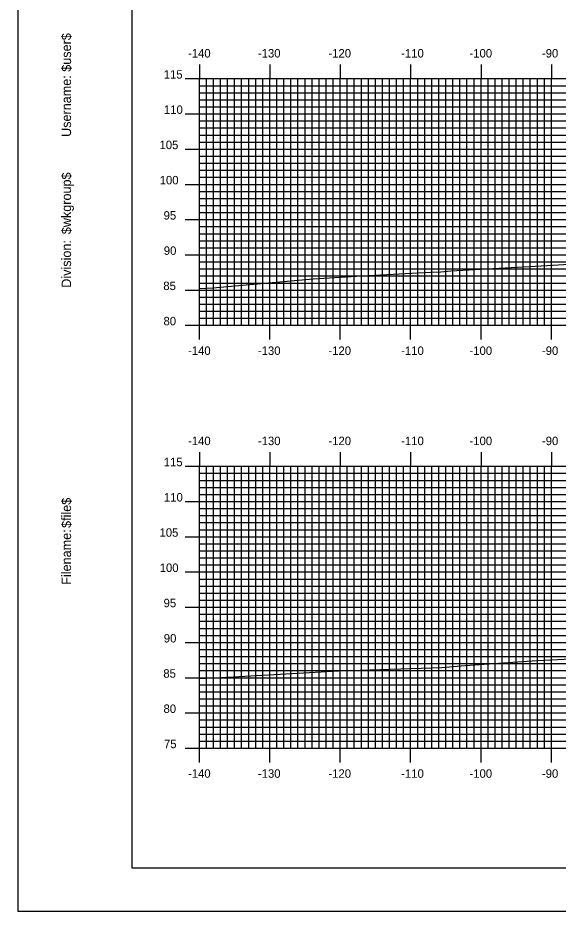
# Model space of a CAD drawing. Extents: x 879 to 1222, y -1658 to -1438.
# Drawn here: x 878.9 to 955.6, y -1657.7 to -1531 of the extents above; entities that cross this region are included whole.
import ezdxf

# ---------------------------------------------------------------- set-up
doc = ezdxf.new("R2010")
doc.units = 0
for name, color, linetype in [('BORDER', 7, 'Continuous'), ('H_V ANNOTATION', 7, 'Continuous'), ('MAJOR', 7, 'Continuous'), ('MINOR', 7, 'Continuous'), ('PLOT BOUNDARY', 7, 'Continuous'), ('S_Roadway_Centerline', 7, 'Continuous')]:
    doc.layers.add(name, color=color, linetype=linetype)

msp = doc.modelspace()

# ---------------------------------------------------------------- linework, layer by layer
at = {"layer": 'BORDER'}
msp.add_lwpolyline([(895.05, -1651.6), (1215.05, -1651.6), (1215.05, -1441.6), (895.05, -1441.6)], close=True, dxfattribs=at)
at = {"layer": 'MAJOR'}
for p, q in [((904.65, -1537.6), (904.65, -1539.6)), ((914.65, -1537.6), (914.65, -1539.6)), ((924.65, -1537.6), (924.65, -1539.6)), ((934.65, -1537.6), (934.65, -1539.6)), ((944.65, -1537.6), (944.65, -1539.6)), ((954.65, -1537.6), (954.65, -1539.6)), ((902.64, -1539.6), (904.65, -1539.6)), ((904.65, -1539.6), (1184.65, -1539.6)), ((904.65, -1574.6), (904.65, -1539.6)), ((904.65, -1574.6), (904.65, -1539.6)), ((904.65, -1539.6), (1184.65, -1539.6)), ((914.65, -1574.6), (914.65, -1539.6)), ((924.65, -1574.6), (924.65, -1539.6)), ((934.65, -1574.6), (934.65, -1539.6)), ((944.65, -1574.6), (944.65, -1539.6)), ((954.65, -1574.6), (954.65, -1539.6)), ((902.64, -1544.6), (904.65, -1544.6)), ((904.65, -1544.6), (1184.65, -1544.6)), ((902.64, -1549.6), (904.65, -1549.6)), ((904.65, -1549.6), (1184.65, -1549.6)), ((902.64, -1554.6), (904.65, -1554.6)), ((904.65, -1554.6), (1184.65, -1554.6)), ((902.64, -1559.6), (904.65, -1559.6)), ((904.65, -1559.6), (1184.65, -1559.6)), ((902.64, -1564.6), (904.65, -1564.6)), ((904.65, -1564.6), (1184.65, -1564.6)), ((902.64, -1569.6), (904.65, -1569.6)), ((904.65, -1569.6), (1184.65, -1569.6)), ((902.64, -1574.6), (904.65, -1574.6)), ((904.65, -1574.6), (1184.65, -1574.6)), ((904.65, -1574.6), (1184.65, -1574.6)), ((904.65, -1576.61), (904.65, -1574.6)), ((914.65, -1576.61), (914.65, -1574.6)), ((924.65, -1576.61), (924.65, -1574.6)), ((934.65, -1576.61), (934.65, -1574.6)), ((944.65, -1576.61), (944.65, -1574.6)), ((954.65, -1576.61), (954.65, -1574.6)), ((904.65, -1592.6), (904.65, -1594.6)), ((914.65, -1592.6), (914.65, -1594.6)), ((924.65, -1592.6), (924.65, -1594.6)), ((934.65, -1592.6), (934.65, -1594.6)), ((944.65, -1592.6), (944.65, -1594.6)), ((954.65, -1592.6), (954.65, -1594.6)), ((902.64, -1594.6), (904.65, -1594.6)), ((904.65, -1594.6), (1184.65, -1594.6)), ((904.65, -1634.6), (904.65, -1594.6)), ((904.65, -1634.6), (904.65, -1594.6)), ((904.65, -1594.6), (1184.65, -1594.6)), ((914.65, -1634.6), (914.65, -1594.6)), ((924.65, -1634.6), (924.65, -1594.6)), ((934.65, -1634.6), (934.65, -1594.6)), ((944.65, -1634.6), (944.65, -1594.6)), ((954.65, -1634.6), (954.65, -1594.6)), ((902.64, -1599.6), (904.65, -1599.6)), ((904.65, -1599.6), (1184.65, -1599.6)), ((902.64, -1604.6), (904.65, -1604.6)), ((904.65, -1604.6), (1184.65, -1604.6)), ((902.64, -1609.6), (904.65, -1609.6)), ((904.65, -1609.6), (1184.65, -1609.6)), ((902.64, -1614.6), (904.65, -1614.6)), ((904.65, -1614.6), (1184.65, -1614.6)), ((902.64, -1619.6), (904.65, -1619.6)), ((904.65, -1619.6), (1184.65, -1619.6)), ((902.64, -1624.6), (904.65, -1624.6)), ((904.65, -1624.6), (1184.65, -1624.6)), ((902.64, -1629.6), (904.65, -1629.6)), ((904.65, -1629.6), (1184.65, -1629.6)), ((902.64, -1634.6), (904.65, -1634.6)), ((904.65, -1634.6), (1184.65, -1634.6)), ((904.65, -1634.6), (1184.65, -1634.6)), ((904.65, -1636.61), (904.65, -1634.6)), ((914.65, -1636.61), (914.65, -1634.6)), ((924.65, -1636.61), (924.65, -1634.6)), ((934.65, -1636.61), (934.65, -1634.6)), ((944.65, -1636.61), (944.65, -1634.6)), ((954.65, -1636.61), (954.65, -1634.6))]:
    msp.add_line(p, q, dxfattribs=at)
at = {"layer": 'MINOR'}
for p, q in [((905.65, -1574.6), (905.65, -1539.6)), ((906.65, -1574.6), (906.65, -1539.6)), ((907.65, -1574.6), (907.65, -1539.6)), ((908.65, -1574.6), (908.65, -1539.6)), ((909.65, -1574.6), (909.65, -1539.6)), ((910.65, -1574.6), (910.65, -1539.6)), ((911.65, -1574.6), (911.65, -1539.6)), ((912.65, -1574.6), (912.65, -1539.6)), ((913.65, -1574.6), (913.65, -1539.6)), ((915.65, -1574.6), (915.65, -1539.6)), ((916.65, -1574.6), (916.65, -1539.6)), ((917.65, -1574.6), (917.65, -1539.6)), ((918.65, -1574.6), (918.65, -1539.6)), ((919.65, -1574.6), (919.65, -1539.6)), ((920.65, -1574.6), (920.65, -1539.6)), ((921.65, -1574.6), (921.65, -1539.6)), ((922.65, -1574.6), (922.65, -1539.6)), ((923.65, -1574.6), (923.65, -1539.6)), ((925.65, -1574.6), (925.65, -1539.6)), ((926.65, -1574.6), (926.65, -1539.6)), ((927.65, -1574.6), (927.65, -1539.6)), ((928.65, -1574.6), (928.65, -1539.6)), ((929.65, -1574.6), (929.65, -1539.6)), ((930.65, -1574.6), (930.65, -1539.6)), ((931.65, -1574.6), (931.65, -1539.6)), ((932.65, -1574.6), (932.65, -1539.6)), ((933.65, -1574.6), (933.65, -1539.6)), ((935.65, -1574.6), (935.65, -1539.6)), ((936.65, -1574.6), (936.65, -1539.6)), ((937.65, -1574.6), (937.65, -1539.6)), ((938.65, -1574.6), (938.65, -1539.6)), ((939.65, -1574.6), (939.65, -1539.6)), ((940.65, -1574.6), (940.65, -1539.6)), ((941.65, -1574.6), (941.65, -1539.6)), ((942.65, -1574.6), (942.65, -1539.6)), ((943.65, -1574.6), (943.65, -1539.6)), ((945.65, -1574.6), (945.65, -1539.6)), ((946.65, -1574.6), (946.65, -1539.6)), ((947.65, -1574.6), (947.65, -1539.6)), ((948.65, -1574.6), (948.65, -1539.6)), ((949.65, -1574.6), (949.65, -1539.6)), ((950.65, -1574.6), (950.65, -1539.6)), ((951.65, -1574.6), (951.65, -1539.6)), ((952.65, -1574.6), (952.65, -1539.6)), ((953.65, -1574.6), (953.65, -1539.6)), ((904.65, -1540.6), (1184.65, -1540.6)), ((904.65, -1540.6), (906.65, -1540.6)), ((904.65, -1541.6), (1184.65, -1541.6)), ((904.65, -1541.6), (906.65, -1541.6)), ((904.65, -1542.6), (1184.65, -1542.6)), ((904.65, -1542.6), (906.65, -1542.6)), ((904.65, -1543.6), (1184.65, -1543.6)), ((904.65, -1543.6), (906.65, -1543.6)), ((904.65, -1545.6), (1184.65, -1545.6)), ((904.65, -1545.6), (906.65, -1545.6)), ((904.65, -1546.6), (1184.65, -1546.6)), ((904.65, -1546.6), (906.65, -1546.6)), ((904.65, -1547.6), (1184.65, -1547.6)), ((904.65, -1547.6), (906.65, -1547.6)), ((904.65, -1548.6), (1184.65, -1548.6)), ((904.65, -1548.6), (906.65, -1548.6)), ((904.65, -1550.6), (1184.65, -1550.6)), ((904.65, -1550.6), (906.65, -1550.6)), ((904.65, -1551.6), (1184.65, -1551.6)), ((904.65, -1551.6), (906.65, -1551.6)), ((904.65, -1552.6), (1184.65, -1552.6)), ((904.65, -1552.6), (906.65, -1552.6)), ((904.65, -1553.6), (1184.65, -1553.6)), ((904.65, -1553.6), (906.65, -1553.6)), ((904.65, -1555.6), (1184.65, -1555.6)), ((904.65, -1555.6), (906.65, -1555.6)), ((904.65, -1556.6), (1184.65, -1556.6)), ((904.65, -1556.6), (906.65, -1556.6)), ((904.65, -1557.6), (1184.65, -1557.6)), ((904.65, -1557.6), (906.65, -1557.6)), ((904.65, -1558.6), (1184.65, -1558.6)), ((904.65, -1558.6), (906.65, -1558.6)), ((904.65, -1560.6), (1184.65, -1560.6)), ((904.65, -1560.6), (906.65, -1560.6)), ((904.65, -1561.6), (1184.65, -1561.6)), ((904.65, -1561.6), (906.65, -1561.6)), ((904.65, -1562.6), (1184.65, -1562.6)), ((904.65, -1562.6), (906.65, -1562.6)), ((904.65, -1563.6), (1184.65, -1563.6)), ((904.65, -1563.6), (906.65, -1563.6)), ((904.65, -1565.6), (1184.65, -1565.6)), ((904.65, -1565.6), (906.65, -1565.6)), ((904.65, -1566.6), (1184.65, -1566.6)), ((904.65, -1566.6), (906.65, -1566.6)), ((904.65, -1567.6), (1184.65, -1567.6)), ((904.65, -1567.6), (906.65, -1567.6)), ((904.65, -1568.6), (1184.65, -1568.6)), ((904.65, -1568.6), (906.65, -1568.6)), ((904.65, -1570.6), (1184.65, -1570.6)), ((904.65, -1570.6), (906.65, -1570.6)), ((904.65, -1571.6), (1184.65, -1571.6)), ((904.65, -1571.6), (906.65, -1571.6)), ((904.65, -1572.6), (1184.65, -1572.6)), ((904.65, -1572.6), (906.65, -1572.6)), ((904.65, -1573.6), (1184.65, -1573.6)), ((904.65, -1573.6), (906.65, -1573.6)), ((904.65, -1595.6), (1184.65, -1595.6)), ((904.65, -1595.6), (906.65, -1595.6)), ((905.65, -1634.6), (905.65, -1594.6)), ((906.65, -1634.6), (906.65, -1594.6)), ((907.65, -1634.6), (907.65, -1594.6)), ((908.65, -1634.6), (908.65, -1594.6)), ((909.65, -1634.6), (909.65, -1594.6)), ((910.65, -1634.6), (910.65, -1594.6)), ((911.65, -1634.6), (911.65, -1594.6)), ((912.65, -1634.6), (912.65, -1594.6)), ((913.65, -1634.6), (913.65, -1594.6)), ((915.65, -1634.6), (915.65, -1594.6)), ((916.65, -1634.6), (916.65, -1594.6)), ((917.65, -1634.6), (917.65, -1594.6)), ((918.65, -1634.6), (918.65, -1594.6)), ((919.65, -1634.6), (919.65, -1594.6)), ((920.65, -1634.6), (920.65, -1594.6)), ((921.65, -1634.6), (921.65, -1594.6)), ((922.65, -1634.6), (922.65, -1594.6)), ((923.65, -1634.6), (923.65, -1594.6)), ((925.65, -1634.6), (925.65, -1594.6)), ((926.65, -1634.6), (926.65, -1594.6)), ((927.65, -1634.6), (927.65, -1594.6)), ((928.65, -1634.6), (928.65, -1594.6)), ((929.65, -1634.6), (929.65, -1594.6)), ((930.65, -1634.6), (930.65, -1594.6)), ((931.65, -1634.6), (931.65, -1594.6)), ((932.65, -1634.6), (932.65, -1594.6)), ((933.65, -1634.6), (933.65, -1594.6)), ((935.65, -1634.6), (935.65, -1594.6)), ((936.65, -1634.6), (936.65, -1594.6)), ((937.65, -1634.6), (937.65, -1594.6)), ((938.65, -1634.6), (938.65, -1594.6)), ((939.65, -1634.6), (939.65, -1594.6)), ((940.65, -1634.6), (940.65, -1594.6)), ((941.65, -1634.6), (941.65, -1594.6)), ((942.65, -1634.6), (942.65, -1594.6)), ((943.65, -1634.6), (943.65, -1594.6)), ((945.65, -1634.6), (945.65, -1594.6)), ((946.65, -1634.6), (946.65, -1594.6)), ((947.65, -1634.6), (947.65, -1594.6)), ((948.65, -1634.6), (948.65, -1594.6)), ((949.65, -1634.6), (949.65, -1594.6)), ((950.65, -1634.6), (950.65, -1594.6)), ((951.65, -1634.6), (951.65, -1594.6)), ((952.65, -1634.6), (952.65, -1594.6)), ((953.65, -1634.6), (953.65, -1594.6)), ((904.65, -1596.6), (1184.65, -1596.6)), ((904.65, -1596.6), (906.65, -1596.6)), ((904.65, -1597.6), (1184.65, -1597.6)), ((904.65, -1597.6), (906.65, -1597.6)), ((904.65, -1598.6), (1184.65, -1598.6)), ((904.65, -1598.6), (906.65, -1598.6)), ((904.65, -1600.6), (1184.65, -1600.6)), ((904.65, -1600.6), (906.65, -1600.6)), ((904.65, -1601.6), (1184.65, -1601.6)), ((904.65, -1601.6), (906.65, -1601.6)), ((904.65, -1602.6), (1184.65, -1602.6)), ((904.65, -1602.6), (906.65, -1602.6)), ((904.65, -1603.6), (1184.65, -1603.6)), ((904.65, -1603.6), (906.65, -1603.6)), ((904.65, -1605.6), (1184.65, -1605.6)), ((904.65, -1605.6), (906.65, -1605.6)), ((904.65, -1606.6), (1184.65, -1606.6)), ((904.65, -1606.6), (906.65, -1606.6)), ((904.65, -1607.6), (1184.65, -1607.6)), ((904.65, -1607.6), (906.65, -1607.6)), ((904.65, -1608.6), (1184.65, -1608.6)), ((904.65, -1608.6), (906.65, -1608.6)), ((904.65, -1610.6), (1184.65, -1610.6)), ((904.65, -1610.6), (906.65, -1610.6)), ((904.65, -1611.6), (1184.65, -1611.6)), ((904.65, -1611.6), (906.65, -1611.6)), ((904.65, -1612.6), (1184.65, -1612.6)), ((904.65, -1612.6), (906.65, -1612.6)), ((904.65, -1613.6), (1184.65, -1613.6)), ((904.65, -1613.6), (906.65, -1613.6)), ((904.65, -1615.6), (1184.65, -1615.6)), ((904.65, -1615.6), (906.65, -1615.6)), ((904.65, -1616.6), (1184.65, -1616.6)), ((904.65, -1616.6), (906.65, -1616.6)), ((904.65, -1617.6), (1184.65, -1617.6)), ((904.65, -1617.6), (906.65, -1617.6)), ((904.65, -1618.6), (1184.65, -1618.6)), ((904.65, -1618.6), (906.65, -1618.6)), ((904.65, -1620.6), (1184.65, -1620.6)), ((904.65, -1620.6), (906.65, -1620.6)), ((904.65, -1621.6), (1184.65, -1621.6)), ((904.65, -1621.6), (906.65, -1621.6)), ((904.65, -1622.6), (1184.65, -1622.6)), ((904.65, -1622.6), (906.65, -1622.6)), ((904.65, -1623.6), (1184.65, -1623.6)), ((904.65, -1623.6), (906.65, -1623.6)), ((904.65, -1625.6), (1184.65, -1625.6)), ((904.65, -1625.6), (906.65, -1625.6)), ((904.65, -1626.6), (1184.65, -1626.6)), ((904.65, -1626.6), (906.65, -1626.6)), ((904.65, -1627.6), (1184.65, -1627.6)), ((904.65, -1627.6), (906.65, -1627.6)), ((904.65, -1628.6), (1184.65, -1628.6)), ((904.65, -1628.6), (906.65, -1628.6)), ((904.65, -1630.6), (1184.65, -1630.6)), ((904.65, -1630.6), (906.65, -1630.6)), ((904.65, -1631.6), (1184.65, -1631.6)), ((904.65, -1631.6), (906.65, -1631.6)), ((904.65, -1632.6), (1184.65, -1632.6)), ((904.65, -1632.6), (906.65, -1632.6)), ((904.65, -1633.6), (1184.65, -1633.6)), ((904.65, -1633.6), (906.65, -1633.6))]:
    msp.add_line(p, q, dxfattribs=at)
at = {"layer": 'PLOT BOUNDARY'}
msp.add_lwpolyline([(878.86, -1657.72), (1218.86, -1657.72), (1218.86, -1437.72), (878.86, -1437.72)], close=True, dxfattribs=at)
at = {"layer": 'S_Roadway_Centerline'}
for points in [[(904.65, -1569.39), (906.57, -1569.27), (920.82, -1568), (927.72, -1567.6), (937.47, -1567.07), (938.95, -1567), (940.37, -1566.88), (954.06, -1566.11), (957.1, -1565.94), (970.54, -1565.45), (981.3, -1564.54), (986.76, -1564.33), (997.58, -1564.13), (1003.63, -1564.01), (1010.92, -1563.72), (1020.27, -1563.67), (1029.13, -1563.37), (1035.94, -1563.09)], [(904.65, -1624.72), (905.67, -1624.65), (909.42, -1624.47), (921.92, -1623.77), (925.24, -1623.6), (926.03, -1623.57), (939.03, -1623.13), (942.41, -1622.85), (952.55, -1622.18), (959.41, -1621.83), (966.93, -1621.24), (977.01, -1620.75), (981.23, -1620.64), (993.73, -1620.44), (997.78, -1620.14), (1010.31, -1619.24), (1022, -1619.15), (1027.5, -1618.88), (1036.74, -1618.64)]]:
    msp.add_lwpolyline(points, dxfattribs=at)

# ---------------------------------------------------------------- texts
at = {"layer": 'BORDER'}
for s, p in [('$user$', (886.42, -1538.62)), ('Username:', (886.42, -1547.87)), ('$wkgroup$', (886.42, -1561.67)), ('Division:', (886.42, -1569.27)), ('$file$', (886.42, -1603.35)), ('Filename:', (886.42, -1611.41))]:
    msp.add_text(s, height=1.339, rotation=90, dxfattribs=at).set_placement(p)
at = {"layer": 'H_V ANNOTATION'}
for s, p in [('-140', (903.03, -1536.6)), ('-130', (912.96, -1536.6)), ('-120', (922.97, -1536.6)), ('-110', (933.31, -1536.6)), ('-100', (943.01, -1536.6)), ('-90', (953.3, -1536.6)), ('115', (899.58, -1539.6)), ('110', (899.61, -1544.6)), ('105', (898.98, -1549.6)), ('100', (899.01, -1554.6)), ('95', (899.56, -1559.6)), ('90', (899.59, -1564.6)), ('85', (899.52, -1569.6)), ('80', (899.55, -1574.6)), ('-140', (903.03, -1578.8)), ('-130', (912.96, -1578.8)), ('-120', (922.97, -1578.8)), ('-110', (933.31, -1578.8)), ('-100', (943.01, -1578.8)), ('-90', (953.3, -1578.8)), ('-140', (903.03, -1591.6)), ('-130', (912.96, -1591.6)), ('-120', (922.97, -1591.6)), ('-110', (933.31, -1591.6)), ('-100', (943.01, -1591.6)), ('-90', (953.3, -1591.6)), ('115', (899.58, -1594.6)), ('110', (899.61, -1599.6)), ('105', (898.98, -1604.6)), ('100', (899.01, -1609.6)), ('95', (899.56, -1614.6)), ('90', (899.59, -1619.6)), ('85', (899.52, -1624.6)), ('80', (899.55, -1629.6)), ('75', (899.62, -1634.6)), ('-140', (903.03, -1638.8)), ('-130', (912.96, -1638.8)), ('-120', (922.97, -1638.8)), ('-110', (933.31, -1638.8)), ('-100', (943.01, -1638.8)), ('-90', (953.3, -1638.8))]:
    msp.add_text(s, height=1.2, dxfattribs=at).set_placement(p)
at = {"layer": 'MAJOR'}
for p in [(904.64, -1574.6), (904.64, -1634.6)]:
    msp.add_text('-', height=0.012, dxfattribs=at).set_placement(p)

doc.saveas('drawing.dxf')
